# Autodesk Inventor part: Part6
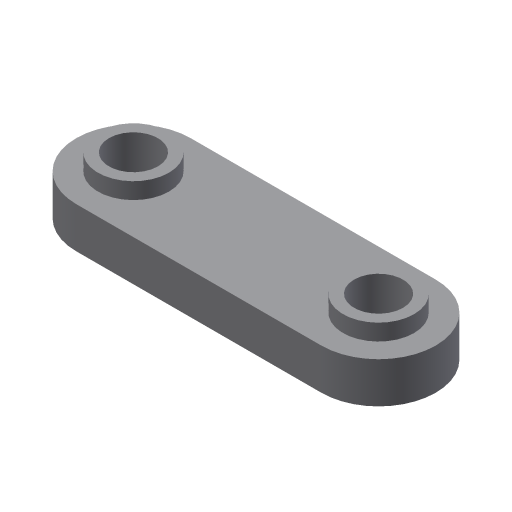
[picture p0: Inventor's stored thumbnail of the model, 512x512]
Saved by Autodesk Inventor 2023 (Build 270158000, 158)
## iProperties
Created: 2002-01
Part Number: Part6
Document SubType Name: Modeling
Designer: ***
Density: 1 g/cm^3
Mass: 21.6911 g
Surface Area: 77.1136 cm^2
Volume: 21.6911 cm^3
Material: Generic
Appearance: Default
Control State: 0
Master: False
Checked Out: False
Shininess: 77.0
Length Units: 11269
Angle Units: 11279
Time Units: 11290
Mass Units: 11283
Length Display Precision: 3
Angle Display Precision: 2
Density: 0.0
Volumn: 0.0
Area: 0.0
PropertySet Name: Model Information
Author: ***
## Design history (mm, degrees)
sketch "Sketch1"
  geometry: L1 (-33.118, 12.346)-(26.882, 12.361); L2 (-33.111, -15.654)-(26.889, -15.639); C1 r 6 at (-33.114, -1.654); C2 r 6 at (26.886, -1.639); A1 r 14 centre (-33.114, -1.654) between (-33.118, 12.346) and (-33.111, -15.654); A2 r 14 centre (26.886, -1.639) between (26.889, -15.639) and (26.882, 12.361)
  constraints: 4 centre point, 4 end point, 4 point on circle, 4 tangent, 2 coincident, 2 equal radius
  dimensions: "d0" = 60 distance of L1.start L1.end; "d1" = 14 radius of A1; "d2" = 12 diameter of C1
extrude "Extrusion1" new body sketch "Sketch1" distance "d3" = 10; taper "d4" = 0 deg
sketch "Sketch2"
  geometry: C1 r 6 at (26.886, -1.639) reference; C2 r 6 at (-33.114, -1.654) reference; C3 r 8.694 at (-33.114, -1.654); C4 r 8.694 at (26.886, -1.639)
  constraints: 2 centre point, 2 coincident, 1 equal radius
extrude "Extrusion2" join sketch "Sketch2" distance "d5" = 4; taper "d6" = 0 deg
body "Solid1"
